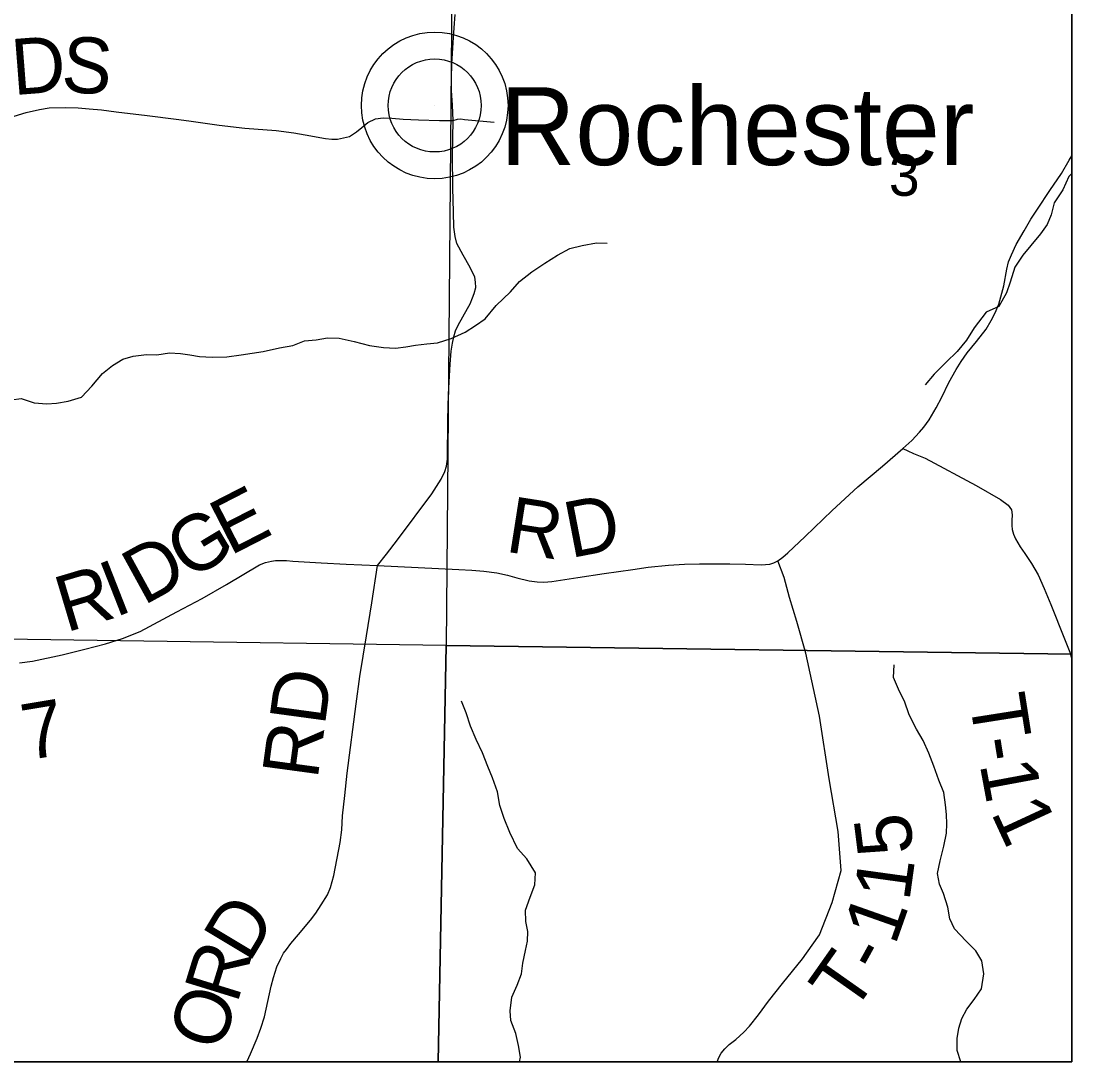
# Model space of a CAD drawing. Extents: x 0 to 34, y 0 to 22.
# Drawn here: x 7.364 to 8.431, y 14.573 to 15.63 of the extents above; entities that cross this region are included whole.
import ezdxf

# ---------------------------------------------------------------- set-up
doc = ezdxf.new("R2010")
doc.units = 0
for name, color, linetype in [('GM_X_Corporation', 7, 'Continuous'), ('GM_X_County_Road', 7, 'Continuous'), ('GM_X_County_Road_Text', 7, 'Continuous'), ('GM_X_Minor_River', 7, 'Continuous'), ('GM_X_Section_Text', 7, 'Continuous'), ('GM_X_Township_Road', 7, 'Continuous'), ('GM_X_Township_Road_Text', 7, 'Continuous'), ('GM_X_Unincorporated', 7, 'Continuous'), ('GM_X_Unincorporated_Location', 7, 'Continuous'), ('GM_X_Unincorporated_Text', 7, 'Continuous'), ('SH_Text', 7, 'Continuous')]:
    doc.layers.add(name, color=color, linetype=linetype)

msp = doc.modelspace()

# ---------------------------------------------------------------- linework, layer by layer
at = {"layer": 'GM_X_Corporation'}
for points in [[(1.6311, 14.5734), (8.4311, 14.5734), (8.4311, 20.028)], [(3.7221, 14.5734), (8.4311, 14.5734), (8.4311, 16.0029), (7.8077, 16.0135), (7.8043, 16.0135), (6.9736, 16.0344), (6.9699, 16.0345), (6.7034, 16.04), (6.6909, 16.0403), (6.6873, 16.0404), (6.4721, 16.0449), (6.4668, 16.045), (5.0373, 16.0816)]]:
    msp.add_lwpolyline(points, dxfattribs=at)
for points in [[(6.8244, 16.0368), (7.8046, 16.0144), (7.7958, 14.9961), (6.804, 15.0104)], [(8.4311, 14.9872), (8.4311, 16.0024), (7.8046, 16.0144), (7.7958, 14.9961)], [(6.7958, 14.5734), (7.7879, 14.5734), (7.7958, 14.9961), (6.804, 15.0104)], [(7.7879, 14.5734), (8.4311, 14.5734), (8.4311, 14.9872), (7.7958, 14.9961)]]:
    msp.add_lwpolyline(points, close=True, dxfattribs=at)
at = {"layer": 'GM_X_County_Road'}
for points in [[(7.7261, 15.0773), (7.7354, 15.0888), (7.7465, 15.1033), (7.7815, 15.1501), (7.7909, 15.1647), (7.7947, 15.1727), (7.7961, 15.1779), (7.7971, 15.1852), (7.7977, 15.2249), (7.7983, 15.2512), (7.7999, 15.2814), (7.8011, 15.2947), (7.8023, 15.3028), (7.8038, 15.3093), (7.8055, 15.3153), (7.808, 15.3211), (7.8175, 15.3379), (7.8204, 15.3429), (7.8227, 15.3488), (7.8242, 15.3532), (7.8259, 15.3594), (7.8257, 15.3647), (7.8251, 15.3699), (7.8203, 15.3797), (7.813, 15.392), (7.8069, 15.4039), (7.805, 15.4112), (7.8037, 15.4206), (7.8032, 15.4358), (7.8028, 15.4605), (7.8024, 15.4932), (7.803, 15.5288), (7.8028, 15.5366), (7.8022, 15.5445), (7.8012, 15.5592), (7.8012, 15.5718), (7.8017, 15.5861), (7.8033, 15.6132), (7.804, 15.623), (7.805, 15.6363)], [(7.3531, 15.5319), (7.3695, 15.537), (7.3832, 15.5401), (7.3929, 15.5417), (7.4099, 15.5419), (7.4224, 15.5417), (7.4337, 15.5406), (7.4459, 15.5395), (7.4609, 15.5377), (7.4923, 15.534), (7.5218, 15.5301), (7.5347, 15.5284), (7.5656, 15.5242), (7.5915, 15.5212), (7.6235, 15.5186), (7.6412, 15.5162), (7.6528, 15.5144), (7.6736, 15.5106), (7.6799, 15.5098), (7.6855, 15.5099), (7.6978, 15.5127), (7.7048, 15.5174), (7.7104, 15.5218), (7.7164, 15.5268), (7.7243, 15.5306), (7.7318, 15.5314), (7.7408, 15.5313), (7.7523, 15.5302), (7.7678, 15.5295), (7.7891, 15.5287), (7.803, 15.5288)], [(7.803, 15.5288), (7.8074, 15.5301), (7.8109, 15.5305), (7.8145, 15.53), (7.8445, 15.527)], [(7.7261, 15.0773), (7.8089, 15.0731), (7.8218, 15.0724), (7.8343, 15.0716), (7.8475, 15.0698), (7.858, 15.0673), (7.8676, 15.0647), (7.88, 15.0616), (7.8882, 15.0606), (7.8952, 15.0604), (7.903, 15.0609), (7.9295, 15.065), (7.9564, 15.0692), (7.9854, 15.0733), (8.0008, 15.0754), (8.0217, 15.0774), (8.0379, 15.0785), (8.0531, 15.079), (8.0839, 15.079), (8.0997, 15.0787), (8.1156, 15.078), (8.1246, 15.0787), (8.1286, 15.0799), (8.1324, 15.0821), (8.1377, 15.0858), (8.1427, 15.09), (8.1603, 15.1065), (8.1877, 15.1329), (8.2138, 15.1569), (8.2389, 15.1779), (8.2595, 15.196), (8.2686, 15.2041), (8.2762, 15.2124), (8.2806, 15.2177), (8.2861, 15.225), (8.2932, 15.2371), (8.2989, 15.2481), (8.3062, 15.2629), (8.3136, 15.2763), (8.3187, 15.2843), (8.3246, 15.2931), (8.3343, 15.3045), (8.3439, 15.3169), (8.3491, 15.326), (8.3533, 15.3336), (8.3569, 15.3424), (8.3618, 15.3611), (8.3649, 15.3781), (8.3668, 15.3855), (8.3698, 15.3926), (8.3745, 15.403), (8.3826, 15.417), (8.3893, 15.4288), (8.3961, 15.4389), (8.4088, 15.4578), (8.4204, 15.4749), (8.4282, 15.4887), (8.4311, 15.493)], [(7.3629, 14.9783), (7.3759, 14.9803), (7.4063, 14.9865), (7.4293, 14.9922), (7.4502, 14.9979), (7.4674, 15.0032), (7.4854, 15.0103), (7.5225, 15.0302), (7.5483, 15.0436), (7.5729, 15.0578), (7.6063, 15.0778), (7.6126, 15.0802), (7.6185, 15.0817), (7.6226, 15.0822), (7.6269, 15.0822), (7.6338, 15.0822), (7.6403, 15.0817), (7.6689, 15.0798), (7.6943, 15.0785), (7.7261, 15.0773)], [(7.5933, 14.5734), (7.5938, 14.5743), (7.5973, 14.5817), (7.6042, 14.5976), (7.6079, 14.6076), (7.6116, 14.6192), (7.6183, 14.6504), (7.6205, 14.6592), (7.6239, 14.6699), (7.628, 14.6784), (7.6308, 14.6837), (7.6339, 14.6876), (7.6383, 14.6937), (7.646, 14.7029), (7.6582, 14.7173), (7.6636, 14.7244), (7.6691, 14.7328), (7.6753, 14.7431), (7.6785, 14.7505), (7.6819, 14.7625), (7.6882, 14.796), (7.69, 14.8089), (7.6908, 14.8231), (7.693, 14.8439), (7.6953, 14.8666), (7.7047, 14.9369), (7.7083, 14.9647), (7.7152, 15.0057), (7.7205, 15.0395), (7.7261, 15.0773)]]:
    msp.add_lwpolyline(points, dxfattribs=at)
at = {"layer": 'GM_X_Minor_River'}
for points in [[(8.4311, 15.475), (8.428, 15.472), (8.422, 15.4583), (8.413, 15.4454), (8.41, 15.4332), (8.4058, 15.4234), (8.3991, 15.4139), (8.3893, 15.4021), (8.3813, 15.3922), (8.373, 15.38), (8.3685, 15.3649), (8.3648, 15.3538), (8.3569, 15.3402), (8.344, 15.3344), (8.332, 15.3185), (8.324, 15.3059), (8.3146, 15.2945), (8.3033, 15.2835), (8.2912, 15.2713), (8.2822, 15.2607)], [(7.3546, 15.2453), (7.3644, 15.2468), (7.3777, 15.2423), (7.3905, 15.2412), (7.4004, 15.242), (7.4121, 15.244), (7.4257, 15.2482), (7.4363, 15.2592), (7.4472, 15.2722), (7.4574, 15.2802), (7.4676, 15.2866), (7.4782, 15.2897), (7.4919, 15.2913), (7.5021, 15.2909), (7.515, 15.2929), (7.5263, 15.2925), (7.5358, 15.291), (7.5456, 15.2892), (7.5585, 15.2885), (7.5733, 15.2889), (7.588, 15.2909), (7.599, 15.2928), (7.61, 15.2943), (7.6266, 15.2982), (7.6403, 15.3005), (7.652, 15.3051), (7.6641, 15.3063), (7.6754, 15.3082), (7.6872, 15.3079), (7.7027, 15.3045), (7.7182, 15.3004), (7.7323, 15.2986), (7.7444, 15.2978), (7.755, 15.299), (7.7648, 15.3009), (7.7762, 15.3021), (7.7872, 15.3033), (7.8011, 15.3075), (7.8151, 15.314), (7.8257, 15.3209), (7.8355, 15.3274), (7.8465, 15.3411), (7.8612, 15.3551), (7.8703, 15.3654), (7.8827, 15.3753), (7.896, 15.3841), (7.9088, 15.3921), (7.9213, 15.3989), (7.9338, 15.402), (7.9485, 15.4047), (7.9595, 15.4044)], [(8.3036, 14.8056), (8.304, 14.8151), (8.3036, 14.8246), (8.3028, 14.8345), (8.3012, 14.847), (8.2959, 14.8595), (8.2909, 14.8735), (8.286, 14.8867), (8.2802, 14.8996), (8.2734, 14.911), (8.2658, 14.9257), (8.2612, 14.9394), (8.2562, 14.9492), (8.2501, 14.9636), (8.2505, 14.9765)], [(7.843, 14.8617), (7.8381, 14.8731), (7.8327, 14.8871), (7.8263, 14.9007), (7.8205, 14.9143), (7.8163, 14.9276), (7.8114, 14.9397)], [(7.8703, 14.5734), (7.8712, 14.5784), (7.8693, 14.5902), (7.8666, 14.6023), (7.8616, 14.6156), (7.8608, 14.6254), (7.8627, 14.6391), (7.8679, 14.6513), (7.8724, 14.663), (7.8739, 14.6737), (7.8765, 14.6866), (7.8784, 14.6961), (7.8787, 14.7059), (7.8768, 14.7158), (7.8764, 14.7275), (7.8813, 14.7408), (7.8858, 14.753), (7.8865, 14.7655), (7.8777, 14.7795), (7.8682, 14.7901), (7.8606, 14.8064), (7.8549, 14.8204), (7.8503, 14.8337), (7.848, 14.8477), (7.843, 14.8617)], [(8.3183, 14.5734), (8.3145, 14.5849), (8.3145, 14.5971), (8.3164, 14.6077), (8.3194, 14.6176), (8.3243, 14.6271), (8.3318, 14.6369), (8.3393, 14.6476), (8.3416, 14.6628), (8.3396, 14.676), (8.3335, 14.6863), (8.3237, 14.6961), (8.3119, 14.7086), (8.3073, 14.7188), (8.305, 14.7305), (8.3008, 14.7442), (8.2966, 14.754), (8.2947, 14.7646), (8.2973, 14.7776), (8.301, 14.7924), (8.3036, 14.8056)]]:
    msp.add_lwpolyline(points, dxfattribs=at)
at = {"layer": 'GM_X_Township_Road'}
for points in [[(8.2595, 15.196), (8.2644, 15.1937), (8.2702, 15.191), (8.282, 15.1863), (8.3339, 15.1585), (8.3586, 15.1442), (8.3663, 15.1383), (8.3697, 15.1336), (8.3703, 15.1286), (8.3701, 15.1228), (8.37, 15.1177), (8.3705, 15.1136), (8.3718, 15.1091), (8.3739, 15.1043), (8.3787, 15.0961), (8.3832, 15.0894), (8.39, 15.0791), (8.3968, 15.0677), (8.403, 15.0539), (8.4097, 15.0376), (8.4234, 15.0027), (8.4291, 14.9893), (8.4311, 14.9823)], [(8.071, 14.5734), (8.0727, 14.578), (8.0751, 14.5825), (8.0787, 14.5867), (8.083, 14.591), (8.0898, 14.5963), (8.0981, 14.6037), (8.1038, 14.6099), (8.1128, 14.6213), (8.1231, 14.6351), (8.1372, 14.6531), (8.1576, 14.6781), (8.1674, 14.6918), (8.1747, 14.7024), (8.1876, 14.7353), (8.1968, 14.7676), (8.1939, 14.8072), (8.1845, 14.8608), (8.1748, 14.9244), (8.161, 14.9881), (8.152, 15.0203), (8.1445, 15.0447), (8.1389, 15.065), (8.1324, 15.0821)]]:
    msp.add_lwpolyline(points, dxfattribs=at)
at = {"layer": 'GM_X_Unincorporated'}
for radius in [0.0744, 0.0472]:
    msp.add_circle((7.7843, 15.5441), radius, dxfattribs=at)
at = {"layer": 'GM_X_Unincorporated_Location'}
msp.add_line((7.7843, 15.5441), (7.7843, 15.5441), dxfattribs=at)
at = {"layer": 'SH_Text'}
for p, q in [((8.4311, 21.373), (8.4311, 14.5734)), ((8.4311, 14.5734), (1.6311, 14.5734))]:
    msp.add_line(p, q, dxfattribs=at)

# ---------------------------------------------------------------- texts
at = {"layer": 'GM_X_County_Road_Text'}
for s, height, rotation, p in [('D', 0.0568, 4.456, (7.3567, 15.5545)), ('S', 0.0568, 355.6815, (7.4043, 15.5584)), ('E', 0.0568, 27.1745, (7.5765, 15.0867)), ('R', 0.0568, 351.0927, (7.855, 15.0915)), ('D', 0.0568, 10.9525, (7.9221, 15.0846)), ('G', 0.0568, 31.0693, (7.5346, 15.0614)), ('D', 0.0568, 28.7869, (7.4886, 15.0361)), ('R', 0.0568, 16.6005, (7.41, 15.0091)), ('I', 0.0568, 21.4447, (7.4597, 15.0242)), ('RD', 0.05682, 82.2794, (7.6653, 14.8594)), ('7', 0.0568, 9.4839, (7.3702, 14.8794)), ('D', 0.0568, 59.0075, (7.5959, 14.6728)), ('R', 0.0568, 72.8168, (7.5836, 14.6315)), ('O', 0.0568, 70.3843, (7.566, 14.5819))]:
    msp.add_text(s, height=height, rotation=rotation, dxfattribs=at).set_placement(p)
at = {"layer": 'GM_X_Section_Text'}
msp.add_text('3', height=0.0419, rotation=0, dxfattribs=at).set_placement((8.2453, 15.4524))
at = {"layer": 'GM_X_Township_Road_Text'}
for s, rotation, p in [('T', 278.972, (8.3267, 14.9424)), ('-', 279.2084, (8.3333, 14.9002)), ('1', 280.5375, (8.3373, 14.8758)), ('1', 294.8098, (8.3484, 14.8267)), ('5', 97.2037, (8.2708, 14.7863)), ('1', 82.1553, (8.266, 14.7356)), ('1', 70.5614, (8.2515, 14.6907)), ('T', 54.8486, (8.2081, 14.6208)), ('-', 61.082, (8.2361, 14.6612))]:
    msp.add_text(s, height=0.0568, rotation=rotation, dxfattribs=at).set_placement(p)
at = {"layer": 'GM_X_Unincorporated_Text'}
msp.add_text('Rochester', height=0.07898, rotation=0, dxfattribs=at).set_placement((7.8508, 15.4836))

doc.saveas('drawing.dxf')
